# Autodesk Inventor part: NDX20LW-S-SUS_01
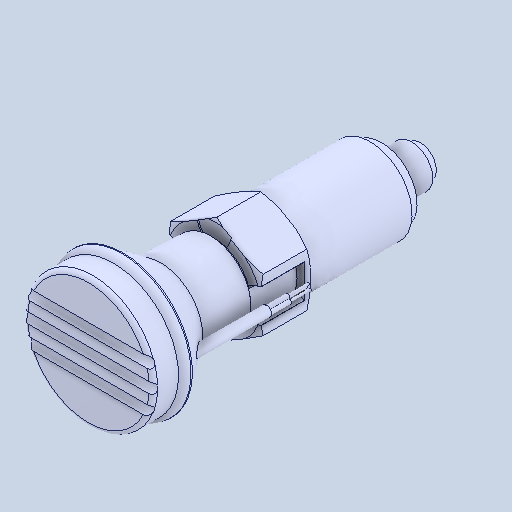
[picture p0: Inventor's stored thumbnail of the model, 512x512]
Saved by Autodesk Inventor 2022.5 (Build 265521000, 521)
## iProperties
Created: 2024-05
Part Number: NDX20LW-S-SUS_01
Material: 一般
Document SubType Name: Modeling
Designer: ImaoCorp
Density: 1 g/cm^3
Appearance: 既定
Author: ImaoCorp
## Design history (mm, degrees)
feature "NDX20LW-S-SUS_01"
node "ソリッド1"
